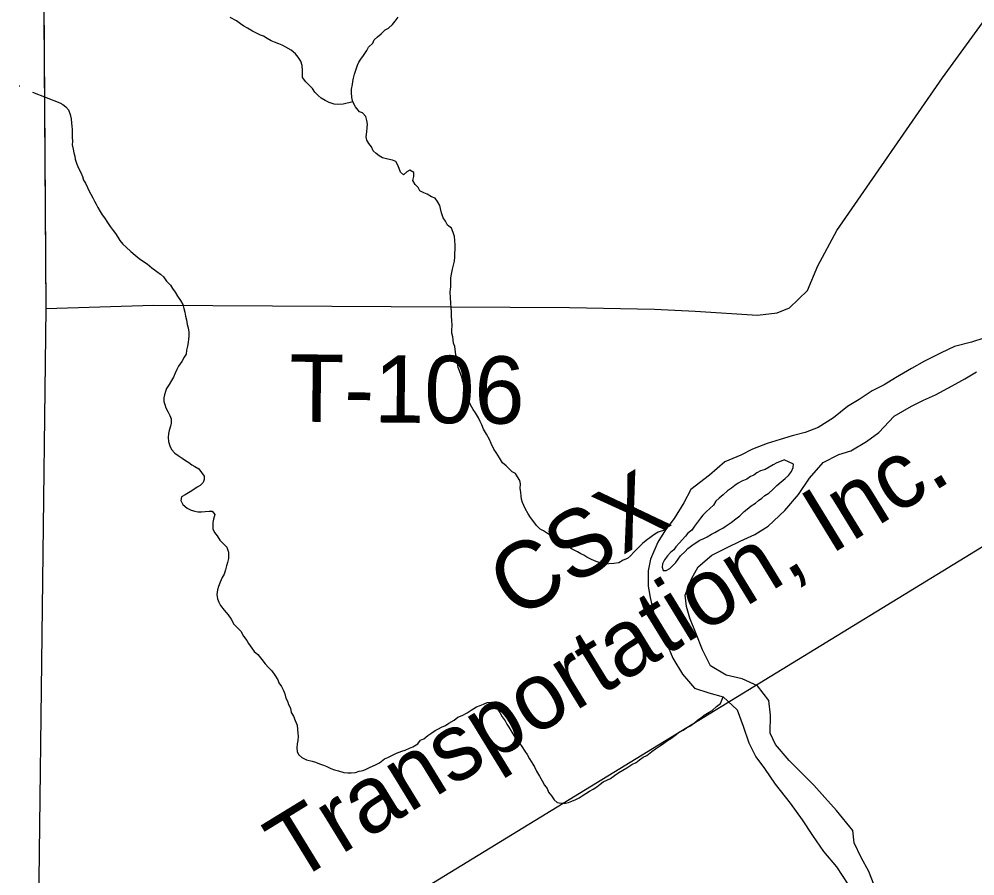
# Model space of a CAD drawing. Extents: x 0 to 1064, y 0 to 440.
# Drawn here: x 110.91 to 123.81, y 382.83 to 394.39 of the extents above; entities that cross this region are included whole.
import ezdxf

# ---------------------------------------------------------------- set-up
doc = ezdxf.new("R2010")
doc.units = 0
for name, color, linetype in [('GM_X_County', 7, 'Continuous'), ('GM_X_Major_River', 7, 'Continuous'), ('GM_X_Minor_River', 7, 'Continuous'), ('GM_X_Rail_Line', 7, 'Continuous'), ('GM_X_Rail_Line_Text', 7, 'Continuous'), ('GM_X_Township', 7, 'Continuous'), ('GM_X_Township_Road', 7, 'Continuous'), ('GM_X_Township_Road_Text', 7, 'Continuous')]:
    doc.layers.add(name, color=color, linetype=linetype)

msp = doc.modelspace()

# ---------------------------------------------------------------- linework, layer by layer
at = {"layer": 'GM_X_County'}
msp.add_lwpolyline([(110.937, 367.797), (111.043, 373.138), (111.062, 374.292), (111.083, 375.478), (111.118, 377.957), (111.181, 382.403), (111.279, 390.484), (111.175, 406.486)], dxfattribs=at)
at = {"layer": 'GM_X_Major_River'}
for points in [[(123.931, 390.082), (123.766, 390.031), (123.534, 389.97), (123.356, 389.884), (123.128, 389.774), (122.956, 389.675), (122.74, 389.547), (122.586, 389.453), (122.426, 389.372), (122.247, 389.255), (122.093, 389.162), (121.901, 389.008), (121.697, 388.88), (121.52, 388.811), (121.343, 388.767), (121.184, 388.716), (121.006, 388.66), (120.81, 388.586), (120.65, 388.505), (120.435, 388.413), (120.231, 388.236), (119.977, 388.041), (119.881, 387.861), (119.754, 387.652), (119.635, 387.497), (119.534, 387.329), (119.431, 387.101), (119.402, 386.943), (119.403, 386.736), (119.429, 386.584), (119.473, 386.388), (119.546, 386.179), (119.65, 385.97), (119.736, 385.767), (119.864, 385.551), (120.028, 385.358), (120.221, 385.299), (120.414, 385.245), (120.603, 385.07), (120.683, 384.849), (120.762, 384.622), (120.854, 384.432), (120.971, 384.277), (121.117, 384.066), (121.317, 383.806), (121.481, 383.583), (121.621, 383.372), (121.767, 383.156), (121.944, 382.951), (122.095, 382.716)], [(122.453, 382.701), (122.379, 382.885), (122.275, 383.076), (122.183, 383.273), (122.163, 383.438), (121.945, 383.711), (121.786, 383.885), (121.639, 384.053), (121.479, 384.209), (121.302, 384.384), (121.119, 384.601), (121.05, 384.755), (121.051, 384.998), (121.031, 385.193), (120.879, 385.392), (120.669, 385.488), (120.452, 385.536), (120.243, 385.663), (120.133, 385.879), (120.048, 386.094), (119.962, 386.303), (119.918, 386.462), (119.903, 386.614), (119.988, 386.837), (120.077, 386.999), (120.263, 387.153), (120.466, 387.257), (120.644, 387.344), (120.841, 387.436), (121.02, 387.547), (121.244, 387.76), (121.431, 387.974), (121.577, 388.196), (121.764, 388.404), (121.973, 388.514), (122.138, 388.565), (122.348, 388.687), (122.515, 388.81), (122.721, 389.03), (122.955, 389.164), (123.115, 389.245), (123.28, 389.32), (123.502, 389.442), (123.674, 389.535), (123.834, 389.628)], [(121.238, 388.44), (121.195, 388.423), (121.14, 388.4), (121.09, 388.376), (121.035, 388.341), (120.98, 388.312), (120.919, 388.295), (120.87, 388.265), (120.826, 388.236), (120.784, 388.219), (120.734, 388.183), (120.667, 388.154), (120.618, 388.125), (120.569, 388.096), (120.525, 388.06), (120.47, 388.025), (120.414, 387.971), (120.358, 387.924), (120.315, 387.882), (120.284, 387.828), (120.234, 387.786), (120.185, 387.739), (120.141, 387.697), (120.11, 387.655), (120.066, 387.601), (120.029, 387.547), (119.991, 387.494), (119.936, 387.452), (119.904, 387.41), (119.861, 387.363), (119.824, 387.321), (119.774, 387.267), (119.749, 387.225), (119.705, 387.189), (119.662, 387.148), (119.624, 387.094), (119.593, 387.04), (119.592, 386.991), (119.603, 386.948), (119.646, 386.947), (119.695, 386.977), (119.775, 387.054), (119.807, 387.102), (119.838, 387.144), (119.9, 387.203), (119.937, 387.245), (119.993, 387.287), (120.048, 387.328), (120.097, 387.357), (120.153, 387.381), (120.196, 387.404), (120.257, 387.439), (120.3, 387.463), (120.355, 387.492), (120.41, 387.521), (120.454, 387.55), (120.521, 387.598), (120.583, 387.645), (120.639, 387.686), (120.695, 387.746), (120.738, 387.775), (120.793, 387.823), (120.849, 387.858), (120.892, 387.894), (120.935, 387.923), (120.978, 387.959), (121.028, 387.994), (121.083, 388.042), (121.139, 388.095), (121.195, 388.143), (121.25, 388.19), (121.294, 388.232), (121.337, 388.286), (121.357, 388.34), (121.364, 388.382)], [(121.364, 388.382), (121.238, 388.44)]]:
    msp.add_lwpolyline(points, dxfattribs=at)
at = {"layer": 'GM_X_Minor_River'}
for points in [[(115.419, 393.275), (115.285, 393.242), (115.23, 393.237), (115.164, 393.244), (115.097, 393.264), (115.043, 393.29), (114.989, 393.321), (114.948, 393.359), (114.906, 393.402), (114.871, 393.452), (114.823, 393.501), (114.782, 393.545), (114.74, 393.6), (114.736, 393.655), (114.737, 393.698), (114.732, 393.765), (114.715, 393.82), (114.68, 393.875), (114.644, 393.919), (114.585, 393.969), (114.513, 394.013), (114.465, 394.038), (114.417, 394.058), (114.362, 394.077), (114.314, 394.096), (114.26, 394.128), (114.212, 394.159), (114.17, 394.172), (114.11, 394.204), (114.062, 394.229), (113.996, 394.267), (113.948, 394.293), (113.9, 394.324), (113.847, 394.368), (113.763, 394.412)], [(116.748, 391.568), (116.694, 391.611), (116.665, 391.661), (116.635, 391.71), (116.613, 391.777), (116.602, 391.832), (116.59, 391.875), (116.561, 391.93), (116.526, 391.974), (116.478, 391.993), (116.418, 392.025), (116.376, 392.044), (116.322, 392.07), (116.298, 392.119), (116.257, 392.156), (116.228, 392.211), (116.241, 392.266), (116.242, 392.321), (116.188, 392.352), (116.145, 392.329), (116.102, 392.287), (116.06, 392.325), (116.043, 392.374), (116.026, 392.417), (115.996, 392.466), (115.954, 392.485), (115.888, 392.499), (115.815, 392.519), (115.774, 392.544), (115.732, 392.575), (115.69, 392.613), (115.667, 392.668), (115.632, 392.711), (115.608, 392.754), (115.597, 392.803), (115.605, 392.87), (115.612, 392.924), (115.613, 392.973), (115.608, 393.022), (115.591, 393.077), (115.549, 393.127), (115.507, 393.14), (115.454, 393.208), (115.419, 393.275), (115.402, 393.331), (115.398, 393.398), (115.399, 393.446), (115.412, 393.507), (115.419, 393.549), (115.426, 393.592), (115.439, 393.646), (115.459, 393.7), (115.478, 393.767), (115.498, 393.809), (115.523, 393.851), (115.56, 393.899), (115.604, 393.965), (115.629, 394.013), (115.685, 394.066), (115.704, 394.109), (115.748, 394.15), (115.797, 394.192), (115.853, 394.245), (115.896, 394.269), (115.952, 394.316), (115.989, 394.364), (116.027, 394.418)], [(110.914, 393.49), (110.922, 393.487)], [(111.094, 393.403), (111.462, 393.258), (111.504, 393.239), (111.546, 393.207), (111.581, 393.164), (111.604, 393.103), (111.615, 393.042), (111.62, 392.987), (111.625, 392.944), (111.63, 392.902), (111.629, 392.841), (111.628, 392.798), (111.633, 392.737), (111.632, 392.695), (111.643, 392.634), (111.654, 392.585), (111.665, 392.542), (111.67, 392.499), (111.693, 392.432), (111.722, 392.37), (111.745, 392.321), (111.768, 392.266), (111.785, 392.217), (111.809, 392.174), (111.838, 392.118), (111.861, 392.069), (111.884, 392.026), (111.908, 391.977), (111.931, 391.934), (111.954, 391.891), (111.978, 391.848), (112.007, 391.792), (112.036, 391.749), (112.066, 391.706), (112.107, 391.644), (112.142, 391.589), (112.183, 391.539), (112.213, 391.496), (112.248, 391.446), (112.271, 391.403), (112.313, 391.354), (112.36, 391.31), (112.42, 391.254), (112.48, 391.204), (112.533, 391.16), (112.581, 391.129), (112.641, 391.085), (112.706, 391.035), (112.772, 390.985), (112.82, 390.947), (112.862, 390.91), (112.903, 390.854), (112.956, 390.798), (112.986, 390.755), (113.021, 390.705), (113.05, 390.65), (113.091, 390.594), (113.121, 390.539), (113.138, 390.484), (113.149, 390.435), (113.16, 390.38), (113.171, 390.331), (113.181, 390.27), (113.193, 390.221), (113.204, 390.166), (113.202, 390.111), (113.201, 390.069), (113.194, 390.026), (113.187, 389.978), (113.174, 389.923), (113.167, 389.869), (113.142, 389.827), (113.11, 389.767), (113.066, 389.707), (113.041, 389.659), (113.022, 389.61), (112.996, 389.556), (112.971, 389.514), (112.939, 389.46), (112.902, 389.406), (112.889, 389.364), (112.876, 389.321), (112.869, 389.279), (112.868, 389.23), (112.879, 389.188), (112.896, 389.145), (112.925, 389.083), (112.949, 389.04), (112.966, 388.997), (112.965, 388.936), (112.958, 388.894), (112.938, 388.839), (112.931, 388.797), (112.924, 388.742), (112.929, 388.687), (112.946, 388.632), (112.969, 388.583), (113.016, 388.533), (113.058, 388.502), (113.112, 388.464)], [(119.635, 387.497), (119.535, 387.467), (119.492, 387.437), (119.443, 387.402), (119.375, 387.355), (119.326, 387.313), (119.27, 387.26), (119.214, 387.2), (119.164, 387.146), (119.121, 387.111), (119.066, 387.088), (119.005, 387.053), (118.938, 387.042), (118.871, 387.037), (118.828, 387.032), (118.762, 387.046), (118.702, 387.071), (118.635, 387.097), (118.575, 387.129), (118.533, 387.154), (118.491, 387.173), (118.449, 387.198), (118.377, 387.237), (118.306, 387.281), (118.264, 387.312), (118.204, 387.344), (118.144, 387.375), (118.084, 387.419), (118.03, 387.457), (117.988, 387.482), (117.946, 387.508), (117.893, 387.557), (117.857, 387.607), (117.816, 387.663), (117.781, 387.712), (117.74, 387.786), (117.705, 387.866), (117.694, 387.909), (117.689, 387.951), (117.684, 388.006), (117.673, 388.055), (117.68, 388.116), (117.669, 388.165), (117.64, 388.214), (117.611, 388.257), (117.569, 388.282), (117.527, 388.32), (117.485, 388.363), (117.438, 388.401), (117.397, 388.469), (117.35, 388.543), (117.32, 388.586), (117.285, 388.66), (117.262, 388.715), (117.222, 388.789), (117.181, 388.857), (117.157, 388.912), (117.134, 388.961), (117.111, 389.01), (117.07, 389.078), (117.041, 389.121), (117.005, 389.183), (116.976, 389.245), (116.953, 389.3), (116.937, 389.385), (116.926, 389.44), (116.903, 389.496), (116.892, 389.544), (116.858, 389.643), (116.84, 389.686), (116.829, 389.741), (116.825, 389.795), (116.808, 389.857), (116.792, 389.973), (116.775, 390.016), (116.764, 390.101), (116.753, 390.15), (116.754, 390.192), (116.756, 390.253), (116.751, 390.326), (116.746, 390.375), (116.748, 390.442), (116.743, 390.491), (116.738, 390.558), (116.733, 390.631), (116.729, 390.704), (116.737, 390.783), (116.738, 390.838), (116.739, 390.898), (116.753, 390.971), (116.76, 391.014), (116.773, 391.068), (116.787, 391.123), (116.794, 391.183), (116.795, 391.226), (116.796, 391.287), (116.797, 391.341), (116.793, 391.402), (116.788, 391.457), (116.771, 391.512), (116.748, 391.568)], [(113.112, 388.464), (113.16, 388.433), (113.202, 388.408), (113.244, 388.376), (113.286, 388.351), (113.34, 388.32), (113.375, 388.27), (113.41, 388.221), (113.409, 388.178), (113.396, 388.136), (113.359, 388.094), (113.316, 388.071), (113.273, 388.041), (113.224, 388.012), (113.156, 387.971), (113.107, 387.941), (113.094, 387.893), (113.123, 387.837), (113.182, 387.788), (113.236, 387.762), (113.285, 387.749), (113.327, 387.742), (113.376, 387.741), (113.424, 387.746), (113.479, 387.751), (113.521, 387.75), (113.557, 387.706), (113.537, 387.64), (113.53, 387.597), (113.529, 387.555), (113.528, 387.512), (113.552, 387.463), (113.587, 387.414), (113.622, 387.358), (113.664, 387.315), (113.717, 387.265), (113.74, 387.197), (113.739, 387.155), (113.738, 387.112), (113.725, 387.058), (113.712, 387.009), (113.698, 386.955), (113.679, 386.9), (113.654, 386.852), (113.628, 386.792), (113.603, 386.732), (113.589, 386.689), (113.582, 386.623), (113.593, 386.568), (113.61, 386.519), (113.633, 386.476), (113.681, 386.414), (113.734, 386.352), (113.775, 386.29), (113.81, 386.222), (113.864, 386.172), (113.905, 386.129), (113.94, 386.061), (113.987, 386.005), (114.011, 385.962), (114.052, 385.9), (114.087, 385.857), (114.135, 385.813), (114.188, 385.745), (114.235, 385.69), (114.277, 385.64), (114.324, 385.596), (114.366, 385.535), (114.407, 385.473), (114.418, 385.43), (114.453, 385.381), (114.483, 385.331), (114.5, 385.282), (114.511, 385.227), (114.534, 385.184), (114.551, 385.141), (114.574, 385.092), (114.585, 385.031), (114.615, 384.982), (114.638, 384.926), (114.666, 384.859), (114.671, 384.804), (114.676, 384.755), (114.681, 384.706), (114.674, 384.652), (114.667, 384.609), (114.66, 384.555), (114.665, 384.506), (114.682, 384.463), (114.73, 384.425), (114.79, 384.393), (114.868, 384.374), (114.911, 384.36), (114.965, 384.341), (115.019, 384.322), (115.067, 384.302), (115.121, 384.277), (115.169, 384.257), (115.224, 384.244), (115.296, 384.224), (115.351, 384.217)], [(120.112, 384.96), (120.156, 384.995), (120.223, 385.036), (120.266, 385.06), (120.322, 385.113), (120.377, 385.155), (120.414, 385.245)], [(115.351, 384.217), (115.393, 384.216), (115.454, 384.221), (115.503, 384.238), (115.558, 384.249), (115.607, 384.272), (115.65, 384.296), (115.723, 384.325), (115.778, 384.354), (115.846, 384.407), (115.889, 384.424), (115.95, 384.454), (116.006, 384.483), (116.079, 384.512), (116.122, 384.523), (116.183, 384.552), (116.226, 384.569), (116.294, 384.61), (116.331, 384.658), (116.374, 384.676), (116.43, 384.723), (116.485, 384.758), (116.528, 384.788), (116.571, 384.811), (116.614, 384.835), (116.669, 384.858), (116.712, 384.887), (116.786, 384.928), (116.835, 384.97), (116.891, 384.993), (116.958, 385.028), (117.013, 385.063), (117.087, 385.11), (117.136, 385.128), (117.179, 385.145), (117.228, 385.168), (117.283, 385.173), (117.342, 385.123), (117.372, 385.074), (117.401, 385.031), (117.43, 384.975), (117.472, 384.919), (117.495, 384.876), (117.524, 384.833), (117.548, 384.79), (117.589, 384.722), (117.624, 384.673), (117.665, 384.617), (117.695, 384.574), (117.736, 384.512), (117.771, 384.463), (117.8, 384.407), (117.847, 384.333), (117.871, 384.29), (117.894, 384.241), (117.935, 384.173), (117.97, 384.111), (118.005, 384.05), (118.04, 384.007), (118.058, 383.957), (118.099, 383.908), (118.134, 383.852), (118.176, 383.815), (118.23, 383.808), (118.285, 383.806), (118.328, 383.818), (118.37, 383.835), (118.426, 383.858), (118.469, 383.882), (118.512, 383.905), (118.561, 383.94), (118.61, 383.97), (118.659, 383.999), (118.708, 384.029), (118.752, 384.064), (118.795, 384.094), (118.844, 384.117), (118.893, 384.14), (118.948, 384.182), (119.004, 384.223), (119.059, 384.252), (119.115, 384.287), (119.182, 384.329), (119.238, 384.358), (119.287, 384.393), (119.336, 384.429), (119.385, 384.452), (119.453, 384.505), (119.502, 384.541), (119.57, 384.588), (119.613, 384.617), (119.663, 384.653), (119.706, 384.682), (119.78, 384.736), (119.823, 384.771), (119.872, 384.794), (119.921, 384.824), (119.964, 384.847), (120.026, 384.894), (120.069, 384.93), (120.112, 384.96)]]:
    msp.add_lwpolyline(points, dxfattribs=at)
at = {"layer": 'GM_X_Rail_Line'}
msp.add_lwpolyline([(111.177, 379.476), (120.304, 385.063), (131.83, 392.117), (142.562, 398.69), (143.768, 399.423)], dxfattribs=at)
at = {"layer": 'GM_X_Township'}
msp.add_lwpolyline([(110.937, 367.797), (111.043, 373.138), (111.062, 374.292), (111.083, 375.478), (111.118, 377.957), (111.181, 382.403), (111.279, 390.484), (111.175, 406.486)], dxfattribs=at)
at = {"layer": 'GM_X_Township_Road'}
for points in [[(111.138, 379.392), (111.181, 382.403), (111.279, 390.484), (111.249, 395.11)], [(111.279, 390.484), (112.727, 390.531), (118.341, 390.496), (119.487, 390.477), (120.034, 390.45), (120.878, 390.393), (121.142, 390.424), (121.31, 390.492), (121.551, 390.726), (121.693, 391.061), (121.947, 391.536), (123.374, 393.595), (124.453, 395.085)]]:
    msp.add_lwpolyline(points, dxfattribs=at)

# ---------------------------------------------------------------- texts
at = {"layer": 'GM_X_Rail_Line_Text'}
for s, height, rotation, p in [('Transportation, Inc.', 0.90606, 31.5006, (114.624, 382.721)), ('CSX', 0.9061, 31.5568, (117.623, 386.27))]:
    msp.add_text(s, height=height, rotation=rotation, dxfattribs=at).set_placement(p)
at = {"layer": 'GM_X_Township_Road_Text'}
msp.add_text('T-106', height=0.9091, rotation=359.4386, dxfattribs=at).set_placement((114.554, 388.958))

doc.saveas('drawing.dxf')
